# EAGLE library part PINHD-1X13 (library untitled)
PIN HEADER
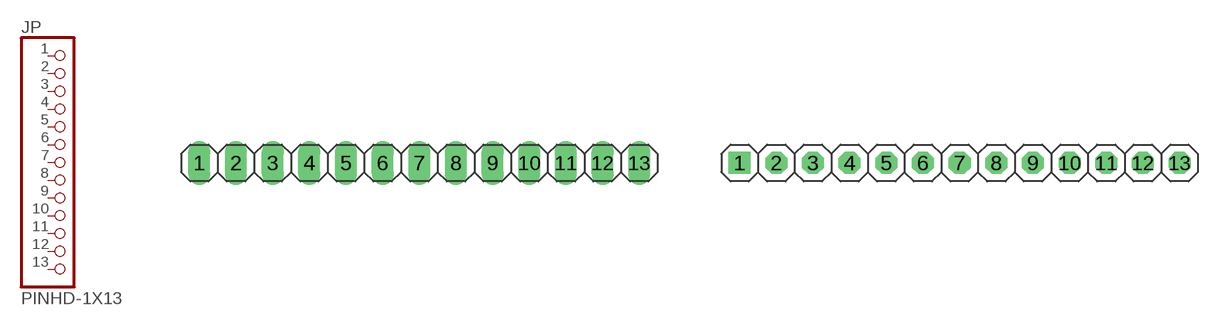
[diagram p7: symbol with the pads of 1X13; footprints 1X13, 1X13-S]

Designator prefix JP

## PINHD-1X13_2.54  [1X13]
1  1  pas
2  2  pas
3  3  pas
4  4  pas
5  5  pas
6  6  pas
7  7  pas
8  8  pas
9  9  pas
10  10  pas
11  11  pas
12  12  pas
13  13  pas

## PINHD-1X13_2.54-S  [1X13-S]
Pads as for 1X13

## PINHD-1X13_2.54-90°  [1X13/90]
Pads as for 1X13

## PINHD-1X13_2.54-90°-S  [1X13/90-S]
Pads as for 1X13

## PINHD-1X13_2.00  [1X13M]
Pads as for 1X13

## PINHD-1X13_2.54-SMD  [1X13SMD]
Pads as for 1X13

## PINHD-1X13_2.54-SMD-90°  [1X13SMD/90]
Pads as for 1X13

## Footprint 1X13 (pad centres in mm)
PIN HEADER - 2.54
drill 1.016 long: 1 -15.24,0; 2 -12.7,0; 3 -10.16,0; 4 -7.62,0; 5 -5.08,0; 6 -2.54,0; 7 0,0; 8 2.54,0; 9 5.08,0; 10 7.62,0; 11 10.16,0; 12 12.7,0; 13 15.24,0

## Footprint 1X13-S (pad centres in mm)
PIN HEADER - 2.54
drill 1.016 square: 1 -15.24,0
drill 1.016 octagon: 2 -12.7,0; 3 -10.16,0; 4 -7.62,0; 5 -5.08,0; 6 -2.54,0; 7 0,0; 8 2.54,0; 9 5.08,0; 10 7.62,0; 11 10.16,0; 12 12.7,0; 13 15.24,0

## Footprint 1X13/90 (pad centres in mm)
PIN HEADER - 2.54 90°
drill 1.016 long: 1 -15.24,-3.81; 2 -12.7,-3.81; 3 -10.16,-3.81; 4 -7.62,-3.81; 5 -5.08,-3.81; 6 -2.54,-3.81; 7 0,-3.81; 8 2.54,-3.81; 9 5.08,-3.81; 10 7.62,-3.81; 11 10.16,-3.81; 12 12.7,-3.81; 13 15.24,-3.81

## Footprint 1X13/90-S (pad centres in mm)
PIN HEADER - 2.54 90°
drill 1.016 square: 1 -15.24,-3.81
drill 1.016 octagon: 2 -12.7,-3.81; 3 -10.16,-3.81; 4 -7.62,-3.81; 5 -5.08,-3.81; 6 -2.54,-3.81; 7 0,-3.81; 8 2.54,-3.81; 9 5.08,-3.81; 10 7.62,-3.81; 11 10.16,-3.81; 12 12.7,-3.81; 13 15.24,-3.81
